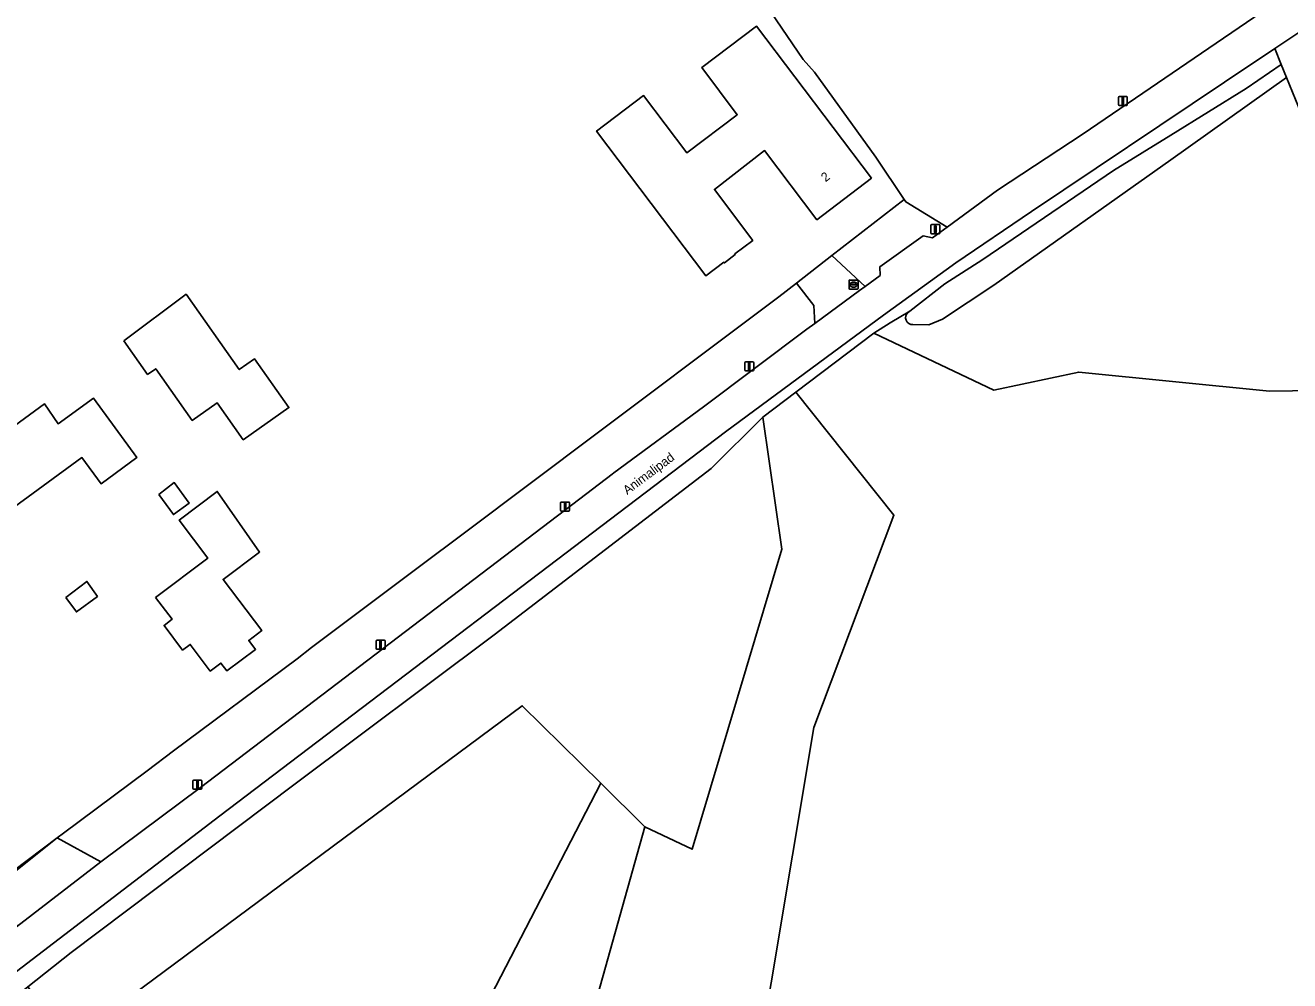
# Model space of a CAD drawing. Extents: x 162156 to 163172, y 378995 to 380779.
# Drawn here: x 162373.7 to 162513.1, y 380228.4 to 380333.8 of the extents above; entities that cross this region are included whole.
import ezdxf

# ---------------------------------------------------------------- set-up
doc = ezdxf.new("R2010")
doc.units = 0
for name, color, linetype in [('IMGEO_Berm_groen', 7, 'Continuous'), ('IMGEO_Brandkraan', 7, 'Continuous'), ('IMGEO_Erf', 7, 'Continuous'), ('IMGEO_Grasland_overig', 7, 'Continuous'), ('IMGEO_Groenvoorziening', 7, 'Continuous'), ('IMGEO_Hek', 7, 'Continuous'), ('IMGEO_Lichtmast', 7, 'Continuous'), ('IMGEO_Loofbos', 7, 'Continuous'), ('IMGEO_Muur', 7, 'Continuous'), ('IMGEO_Openbare_ruimte_label', 7, 'Continuous'), ('IMGEO_Pand', 7, 'Continuous'), ('IMGEO_Pand_nummerreeks', 7, 'Continuous'), ('IMGEO_Pand_vergunning_verleend', 7, 'Continuous'), ('IMGEO_Rijbaan_lokaal_gesloten', 7, 'Continuous'), ('IMGEO_Rijbaan_lokaal_halfverhard', 7, 'Continuous'), ('IMGEO_Voetpad_open', 7, 'Continuous'), ('IMGEO_Waterloop', 7, 'Continuous')]:
    doc.layers.add(name, color=color, linetype=linetype)

msp = doc.modelspace()

# ---------------------------------------------------------------- linework, layer by layer
at = {"layer": 'IMGEO_Berm_groen'}
msp.add_lwpolyline([(162434.07, 380280.96), (162438.4, 380284.26), (162438.58, 380284.4), (162448.48, 380291.7), (162459.87, 380300.26), (162460.75, 380300.9), (162460.66, 380302.88), (162458.72, 380305.32), (162456.79, 380303.81), (162449.57, 380298.41), (162441.18, 380292.1), (162434.83, 380287.34), (162431.27, 380284.67), (162420.34, 380276.48), (162418.94, 380275.41), (162405.25, 380265.15), (162403.66, 380263.89), (162390.04, 380253.73), (162387.11, 380251.53), (162377.9, 380244.68), (162377.2, 380244.15), (162382, 380241.49), (162393, 380249.7)], close=True, dxfattribs=at)
at = {"layer": 'IMGEO_Brandkraan'}
for p, q in [((162464.53, 380304.76), (162464.53, 380305.61)), ((162464.61, 380305.68), (162465.46, 380305.68)), ((162465.46, 380304.68), (162464.61, 380304.68)), ((162464.79, 380305.18), (162464.79, 380305.19)), ((162465.23, 380305.14), (162464.83, 380305.14)), ((162464.84, 380305.23), (162465.23, 380305.23)), ((162465.02, 380305.46), (162465.05, 380305.46)), ((162465.04, 380304.9), (162465.02, 380304.9)), ((162465.28, 380305.19), (162465.28, 380305.18)), ((162465.53, 380305.61), (162465.53, 380304.76))]:
    msp.add_line(p, q, dxfattribs=at)
for points in [[(162464.53, 380304.76), (162464.53, 380305.61)], [(162464.61, 380305.68), (162465.46, 380305.68)], [(162465.46, 380304.68), (162464.61, 380304.68)], [(162465.53, 380305.61), (162465.53, 380304.76)]]:
    msp.add_lwpolyline(points, dxfattribs=at)
for centre, radius, start, end in [((162464.61, 380305.61), 0.0765, 91.552, 178.448), ((162464.61, 380305.61), 0.0765, 91.552, 178.448), ((162464.61, 380304.76), 0.0765, 181.552, 268.448), ((162464.61, 380304.76), 0.0765, 181.552, 268.448), ((162464.83, 380305.19), 0.0403, 85.8775, 175.7526), ((162464.83, 380305.18), 0.0366, 178.938, 274.7102), ((162465.24, 380305.19), 0.0386, 1.7309, 96.639), ((162465.23, 380305.18), 0.043, 264.8664, 352.4533), ((162465.46, 380305.61), 0.0765, 1.552, 88.448), ((162465.46, 380305.61), 0.0765, 1.552, 88.448), ((162465.46, 380304.76), 0.0765, 271.552, 358.448), ((162465.46, 380304.76), 0.0765, 271.552, 358.448)]:
    msp.add_arc(centre, radius, start, end, dxfattribs=at)
for centre, major_axis, ratio, start_param, end_param in [((162465.02, 380305.18), (-0.387, 0.002), 0.722429, 4.712389, 7.853982), ((162465.04, 380305.18), (-0.39, 0.002), 0.717154, 1.570796, 4.712389)]:
    msp.add_ellipse(centre, major_axis=major_axis, ratio=ratio, start_param=start_param, end_param=end_param, dxfattribs=at)
at = {"layer": 'IMGEO_Erf'}
for points in [[(162441.18, 380292.1), (162449.57, 380298.41), (162456.79, 380303.81), (162458.72, 380305.32), (162462.64, 380308.37), (162470.61, 380314.58), (162467.48, 380319.24), (162460.73, 380328.6), (162459.48, 380329.99), (162454.14, 380337.89)], [(162358.49, 380230.04), (162372.26, 380240.2), (162377.2, 380244.15), (162377.9, 380244.68), (162387.11, 380251.53), (162390.04, 380253.73), (162403.66, 380263.89), (162405.25, 380265.15), (162418.94, 380275.41), (162420.34, 380276.48), (162431.27, 380284.67), (162434.83, 380287.34), (162441.18, 380292.1)]]:
    msp.add_lwpolyline(points, dxfattribs=at)
msp.add_lwpolyline([(162436.69, 380322.11), (162441.87, 380326.03), (162446.64, 380319.72), (162452.21, 380323.92), (162448.29, 380329.11), (162454.33, 380333.67), (162467, 380316.93), (162460.98, 380312.34), (162455.21, 380319.96), (162449.68, 380315.67), (162453.92, 380310.05), (162451.93, 380308.57), (162451.98, 380308.51), (162450.79, 380307.57), (162450.73, 380307.65), (162448.72, 380306.16)], close=True, dxfattribs=at)
at = {"layer": 'IMGEO_Grasland_overig'}
msp.add_lwpolyline([(162370.42, 380218.19), (162369.04, 380207.47), (162411.8, 380201.13), (162437.14, 380250.17), (162428.5, 380258.73), (162378.58, 380221.7), (162373.96, 380227.72), (162366.39, 380221.64)], close=True, dxfattribs=at)
at = {"layer": 'IMGEO_Groenvoorziening'}
for points in [[(162493.69, 380317.77), (162500, 380321.67), (162508.34, 380326.82), (162512.19, 380329.47), (162511.48, 380331.21), (162505.93, 380327.51), (162484.67, 380313.25), (162476.32, 380307.57), (162468.33, 380301.8), (162450.89, 380288.94), (162395.15, 380246.57), (162372.73, 380229.41), (162372.69, 380229.38), (162370.26, 380227.56), (162363.86, 380222.76), (162350.25, 380212.01), (162347.18, 380208.96)], [(162366.39, 380221.64), (162373.96, 380227.72), (162378.73, 380231.49), (162403.3, 380250), (162425.4, 380266.56), (162449.31, 380284.9), (162455.03, 380290.55), (162458.66, 380293.31), (162467.25, 380299.83), (162469.05, 380300.96), (162471.22, 380302.24), (162475.11, 380305.26), (162479.3, 380307.95), (162493.69, 380317.77)]]:
    msp.add_lwpolyline(points, dxfattribs=at)
for points in [[(162475.36, 380311.53), (162470.8, 380314.29), (162470.61, 380314.58), (162462.64, 380308.37), (162466.32, 380304.97), (162467.98, 380306.19), (162467.94, 380307.14), (162472.69, 380310.55), (162473.74, 380310.35)], [(162532, 380283.39), (162532.68, 380288.65), (162530.36, 380292.86), (162524.04, 380300.51), (162523.61, 380293.6), (162510.9, 380293.43), (162489.86, 380295.52), (162480.48, 380293.52), (162467.25, 380299.83), (162458.66, 380293.31), (162469.48, 380279.74), (162460.66, 380256.31), (162453.58, 380214.09), (162455.18, 380204.12), (162493.82, 380200.01), (162523.33, 380208.53)], [(162455.03, 380290.55), (162457.1, 380276), (162447.24, 380242.9), (162442, 380245.37), (162430.3, 380203.52), (162441.69, 380197.08), (162520.84, 380187.03), (162523.33, 380208.53), (162493.82, 380200.01), (162455.18, 380204.12), (162453.58, 380214.09), (162460.66, 380256.31), (162469.48, 380279.74), (162458.66, 380293.31)], [(162442, 380245.37), (162447.24, 380242.9), (162457.1, 380276), (162455.03, 380290.55), (162449.31, 380284.9), (162425.4, 380266.56), (162403.3, 380250), (162378.73, 380231.49), (162373.96, 380227.72), (162378.58, 380221.7), (162428.5, 380258.73), (162437.14, 380250.17)]]:
    msp.add_lwpolyline(points, close=True, dxfattribs=at)
at = {"layer": 'IMGEO_Hek'}
for points in [[(162470.61, 380314.58), (162467.48, 380319.24), (162460.73, 380328.6), (162459.48, 380329.99), (162454.14, 380337.89), (162448.06, 380346.22), (162447.12, 380347.84), (162440.5, 380357.48), (162424.53, 380359.77), (162327.51, 380372.72)], [(162470.8, 380314.29), (162470.61, 380314.58)], [(162377.9, 380244.68), (162377.2, 380244.15)], [(162377.2, 380244.15), (162372.39, 380240.52)]]:
    msp.add_lwpolyline(points, dxfattribs=at)
at = {"layer": 'IMGEO_Lichtmast'}
for p, q in [((162494.24, 380325.03), (162494.24, 380325.83)), ((162494.24, 380325.83), (162494.24, 380325.03)), ((162494.34, 380325.93), (162495.12, 380325.93)), ((162495.12, 380325.93), (162494.34, 380325.93)), ((162495.22, 380325.83), (162495.22, 380325.03)), ((162495.22, 380325.03), (162495.22, 380325.83)), ((162495.12, 380324.93), (162494.34, 380324.93)), ((162494.34, 380324.93), (162495.12, 380324.93)), ((162473.55, 380310.89), (162473.55, 380311.69)), ((162473.55, 380311.69), (162473.55, 380310.89)), ((162473.65, 380311.79), (162474.44, 380311.79)), ((162474.44, 380311.79), (162473.65, 380311.79)), ((162474.54, 380311.69), (162474.54, 380310.89)), ((162474.54, 380310.89), (162474.54, 380311.69)), ((162474.44, 380310.79), (162473.65, 380310.79)), ((162473.65, 380310.79), (162474.44, 380310.79)), ((162453.03, 380295.77), (162453.03, 380296.56)), ((162453.03, 380296.56), (162453.03, 380295.77)), ((162453.13, 380296.66), (162453.92, 380296.66)), ((162453.92, 380296.66), (162453.13, 380296.66)), ((162454.02, 380296.56), (162454.02, 380295.77)), ((162454.02, 380295.77), (162454.02, 380296.56)), ((162453.92, 380295.67), (162453.13, 380295.67)), ((162453.13, 380295.67), (162453.92, 380295.67)), ((162432.72, 380280.29), (162432.72, 380281.09)), ((162432.72, 380281.09), (162432.72, 380280.29)), ((162432.82, 380281.19), (162433.61, 380281.19)), ((162433.61, 380281.19), (162432.82, 380281.19)), ((162433.71, 380281.09), (162433.71, 380280.29)), ((162433.71, 380280.29), (162433.71, 380281.09)), ((162433.61, 380280.19), (162432.82, 380280.19)), ((162432.82, 380280.19), (162433.61, 380280.19)), ((162412.38, 380265.05), (162412.38, 380265.85)), ((162412.38, 380265.85), (162412.38, 380265.05)), ((162412.48, 380265.95), (162413.27, 380265.95)), ((162413.27, 380265.95), (162412.48, 380265.95)), ((162413.37, 380265.85), (162413.37, 380265.05)), ((162413.37, 380265.05), (162413.37, 380265.85)), ((162413.27, 380264.95), (162412.48, 380264.95)), ((162412.48, 380264.95), (162413.27, 380264.95)), ((162392.17, 380249.62), (162392.17, 380250.42)), ((162392.17, 380250.42), (162392.17, 380249.62)), ((162392.27, 380250.52), (162393.06, 380250.52)), ((162393.06, 380250.52), (162392.27, 380250.52)), ((162393.16, 380250.42), (162393.16, 380249.62)), ((162393.16, 380249.62), (162393.16, 380250.42)), ((162393.06, 380249.52), (162392.27, 380249.52)), ((162392.27, 380249.52), (162393.06, 380249.52))]:
    msp.add_line(p, q, dxfattribs=at)
for points in [[(162494.65, 380325.81), (162494.81, 380325.81), (162494.81, 380325.06), (162494.65, 380325.06), (162494.65, 380325.81)], [(162473.97, 380311.66), (162474.12, 380311.66), (162474.12, 380310.91), (162473.97, 380310.91), (162473.97, 380311.66)], [(162453.45, 380296.54), (162453.6, 380296.54), (162453.6, 380295.79), (162453.45, 380295.79), (162453.45, 380296.54)], [(162433.14, 380281.07), (162433.29, 380281.07), (162433.29, 380280.32), (162433.14, 380280.32), (162433.14, 380281.07)], [(162412.8, 380265.83), (162412.95, 380265.83), (162412.95, 380265.08), (162412.8, 380265.08), (162412.8, 380265.83)], [(162392.59, 380250.39), (162392.74, 380250.39), (162392.74, 380249.64), (162392.59, 380249.64), (162392.59, 380250.39)]]:
    msp.add_lwpolyline(points, dxfattribs=at)
for centre, start, end in [((162494.34, 380325.83), 90, 180), ((162494.34, 380325.83), 90, 180), ((162495.12, 380325.83), 0, 90), ((162495.12, 380325.83), 360, 90), ((162494.34, 380325.03), 180, 270), ((162494.34, 380325.03), 180, 270), ((162495.12, 380325.03), 270, 0), ((162495.12, 380325.03), 270, 0), ((162473.65, 380311.69), 90, 180), ((162473.65, 380311.69), 90, 180), ((162474.44, 380311.69), 0, 90), ((162474.44, 380311.69), 360, 90), ((162473.65, 380310.89), 180, 270), ((162473.65, 380310.89), 180, 270), ((162474.44, 380310.89), 270, 0), ((162474.44, 380310.89), 270, 0), ((162453.13, 380296.56), 90, 180), ((162453.13, 380296.56), 90, 180), ((162453.92, 380296.56), 0, 90), ((162453.92, 380296.56), 360, 90), ((162453.13, 380295.77), 180, 270), ((162453.13, 380295.77), 180, 270), ((162453.92, 380295.77), 270, 0), ((162453.92, 380295.77), 270, 0), ((162432.82, 380281.09), 90, 180), ((162432.82, 380281.09), 90, 180), ((162433.61, 380281.09), 0, 90), ((162433.61, 380281.09), 360, 90), ((162432.82, 380280.29), 180, 270), ((162432.82, 380280.29), 180, 270), ((162433.61, 380280.29), 270, 0), ((162433.61, 380280.29), 270, 0), ((162412.48, 380265.85), 90, 180), ((162412.48, 380265.85), 90, 180), ((162413.27, 380265.85), 0, 90), ((162413.27, 380265.85), 360, 90), ((162412.48, 380265.05), 180, 270), ((162412.48, 380265.05), 180, 270), ((162413.27, 380265.05), 270, 0), ((162413.27, 380265.05), 270, 0), ((162392.27, 380250.42), 90, 180), ((162392.27, 380250.42), 90, 180), ((162393.06, 380250.42), 0, 90), ((162393.06, 380250.42), 360, 90), ((162392.27, 380249.62), 180, 270), ((162392.27, 380249.62), 180, 270), ((162393.06, 380249.62), 270, 0), ((162393.06, 380249.62), 270, 0)]:
    msp.add_arc(centre, 0.1, start, end, dxfattribs=at)
at = {"layer": 'IMGEO_Loofbos'}
for points in [[(162454.14, 380337.89), (162459.48, 380329.99), (162460.73, 380328.6), (162467.48, 380319.24), (162470.61, 380314.58), (162470.8, 380314.29), (162475.36, 380311.53), (162480.92, 380315.59), (162490.34, 380321.82), (162511.61, 380336.28)], [(162471.07, 380302.12), (162471.22, 380302.24), (162469.05, 380300.96), (162467.25, 380299.83), (162480.48, 380293.52), (162489.86, 380295.52), (162510.9, 380293.43), (162523.61, 380293.6), (162524.04, 380300.51), (162512.79, 380328.01), (162500, 380318.94), (162480.5, 380305.12), (162474.82, 380301.35), (162473.32, 380300.75), (162471.58, 380300.77)], [(162520.84, 380187.03), (162441.69, 380197.08), (162430.3, 380203.52), (162442, 380245.37), (162437.14, 380250.17), (162411.8, 380201.13), (162369.04, 380207.47)]]:
    msp.add_lwpolyline(points, dxfattribs=at)
msp.add_arc((162471.53, 380301.52), 0.759, 127.7765, 273.6127, dxfattribs=at)
at = {"layer": 'IMGEO_Muur'}
for points in [[(162449.57, 380298.41), (162441.18, 380292.1)], [(162434.83, 380287.34), (162441.18, 380292.1)], [(162420.34, 380276.48), (162431.27, 380284.67)], [(162405.25, 380265.15), (162418.94, 380275.41)], [(162418.94, 380275.41), (162420.34, 380276.48)], [(162403.66, 380263.89), (162405.25, 380265.15)], [(162390.04, 380253.73), (162403.66, 380263.89)], [(162387.11, 380251.53), (162390.04, 380253.73)], [(162377.9, 380244.68), (162387.11, 380251.53)]]:
    msp.add_lwpolyline(points, dxfattribs=at)
at = {"layer": 'IMGEO_Pand'}
msp.add_lwpolyline([(162448.72, 380306.16), (162450.73, 380307.65), (162450.79, 380307.57), (162451.98, 380308.51), (162451.93, 380308.57), (162453.92, 380310.05), (162449.68, 380315.67), (162455.21, 380319.96), (162460.98, 380312.34), (162467, 380316.93), (162454.33, 380333.67), (162448.29, 380329.11), (162452.21, 380323.92), (162446.64, 380319.72), (162441.87, 380326.03), (162436.69, 380322.11)], close=True, dxfattribs=at)
at = {"layer": 'IMGEO_Pand_vergunning_verleend'}
for points in [[(162384.55, 380298.98), (162391.42, 380304.11), (162397.29, 380295.81), (162398.96, 380296.99), (162402.76, 380291.62), (162397.73, 380288.06), (162394.84, 380292.14), (162392.09, 380290.2), (162388.07, 380295.89), (162387.18, 380295.27)], [(162366.96, 380285.57), (162375.8, 380292.03), (162377.31, 380289.82), (162381.19, 380292.66), (162385.98, 380286.09), (162382.04, 380283.21), (162379.93, 380286.1), (162371.4, 380279.87), (162370.38, 380281.26), (162369.53, 380280.64), (162367.31, 380283.68), (162367.98, 380284.17)], [(162388.06, 380270.66), (162393.82, 380275.01), (162390.66, 380279.21), (162394.86, 380282.37), (162399.52, 380275.68), (162395.5, 380272.65), (162399.76, 380267.01), (162398.33, 380265.93), (162399.08, 380264.94), (162395.92, 380262.56), (162395.26, 380263.43), (162394.09, 380262.55), (162391.87, 380265.49), (162391.04, 380264.87), (162388.99, 380267.59), (162389.87, 380268.26)], [(162388.41, 380282.01), (162390.11, 380283.34), (162391.76, 380281.08), (162390.02, 380279.81)], [(162378.14, 380270.68), (162380.49, 380272.43), (162381.64, 380270.79), (162379.32, 380269.07)]]:
    msp.add_lwpolyline(points, close=True, dxfattribs=at)
at = {"layer": 'IMGEO_Rijbaan_lokaal_gesloten'}
for points in [[(162347.18, 380208.96), (162350.25, 380212.01), (162363.86, 380222.76), (162370.26, 380227.56), (162372.69, 380229.38), (162372.73, 380229.41), (162395.15, 380246.57), (162450.89, 380288.94), (162468.33, 380301.8), (162476.32, 380307.57), (162484.67, 380313.25), (162505.93, 380327.51), (162511.48, 380331.21), (162514.91, 380333.49), (162527.03, 380341.73)], [(162511.61, 380336.28), (162490.34, 380321.82), (162480.92, 380315.59), (162475.36, 380311.53), (162473.74, 380310.35), (162472.69, 380310.55), (162467.94, 380307.14), (162467.98, 380306.19), (162466.32, 380304.97), (162465.7, 380304.52), (162460.75, 380300.9), (162459.87, 380300.26), (162448.48, 380291.7), (162438.58, 380284.4), (162438.4, 380284.26), (162434.07, 380280.96), (162393, 380249.7), (162382, 380241.49), (162372.73, 380234.33)]]:
    msp.add_lwpolyline(points, dxfattribs=at)
at = {"layer": 'IMGEO_Rijbaan_lokaal_halfverhard'}
msp.add_lwpolyline([(162514.91, 380333.49), (162511.48, 380331.21), (162512.19, 380329.47), (162512.79, 380328.01), (162524.04, 380300.51)], dxfattribs=at)
at = {"layer": 'IMGEO_Voetpad_open'}
for points in [[(162465.7, 380304.52), (162466.32, 380304.97), (162462.64, 380308.37), (162458.72, 380305.32), (162460.66, 380302.88), (162460.75, 380300.9)], [(162382, 380241.49), (162377.2, 380244.15), (162372.26, 380240.2), (162372.73, 380234.33)]]:
    msp.add_lwpolyline(points, close=True, dxfattribs=at)
at = {"layer": 'IMGEO_Waterloop'}
for points in [[(162512.19, 380329.47), (162508.34, 380326.82), (162500, 380321.67), (162493.69, 380317.77), (162479.3, 380307.95), (162475.11, 380305.26), (162471.22, 380302.24)], [(162512.79, 380328.01), (162512.19, 380329.47)], [(162471.58, 380300.77), (162473.32, 380300.75), (162474.82, 380301.35), (162480.5, 380305.12), (162500, 380318.94), (162512.79, 380328.01)], [(162471.22, 380302.24), (162471.07, 380302.12)]]:
    msp.add_lwpolyline(points, dxfattribs=at)
msp.add_arc((162471.53, 380301.52), 0.759, 127.7765, 273.6127, dxfattribs=at)

# ---------------------------------------------------------------- texts
at = {"layer": 'IMGEO_Openbare_ruimte_label'}
msp.add_text('Animalipad', height=1, rotation=36.7438, dxfattribs=at).set_placement((162440.07, 380281.96))
at = {"layer": 'IMGEO_Pand_nummerreeks'}
msp.add_text('2', height=1, rotation=38.4881, dxfattribs=at).set_placement((162461.94, 380316.45))

doc.saveas('drawing.dxf')
